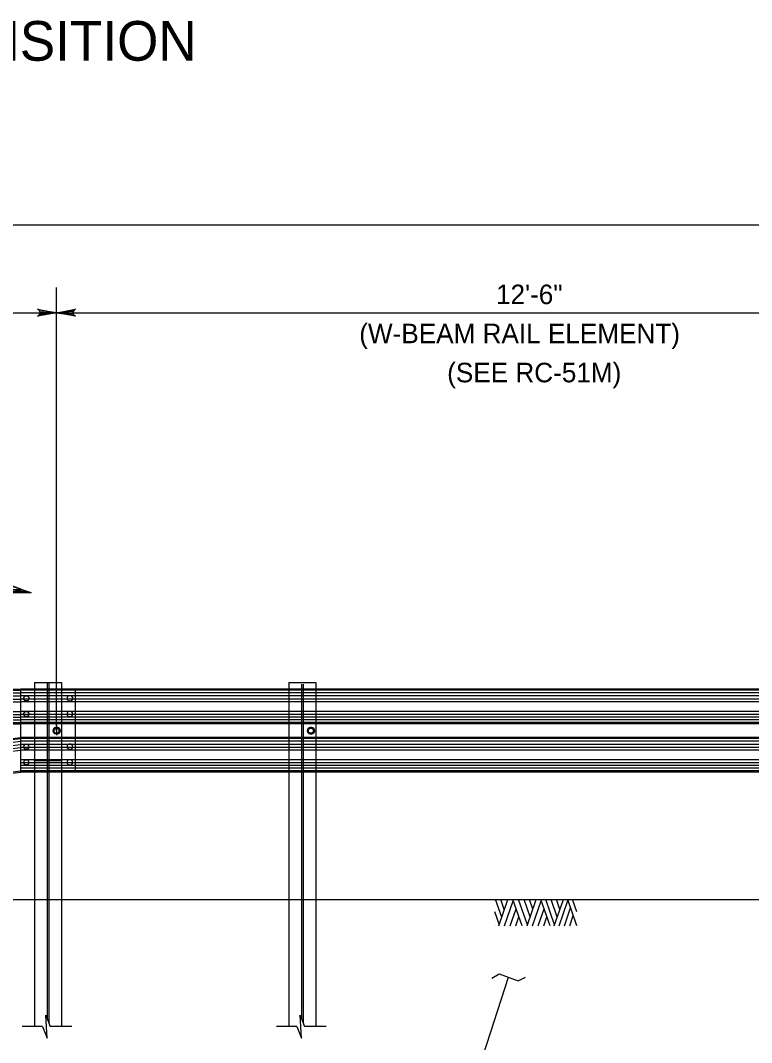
# Model space of a CAD drawing. Extents: x 632007860 to 635435983, y 295418622 to 297794622.
# Drawn here: x 632370402 to 632482682, y 297303010 to 297459928 of the extents above; entities that cross this region are included whole.
import ezdxf

# ---------------------------------------------------------------- set-up
doc = ezdxf.new("R2010")
doc.units = 0
for name, color, linetype in [('2', 7, 'Continuous'), ('S-DETL-DIMS', 7, 'Continuous'), ('S-DETL-T120', 7, 'Continuous'), ('S-DETL-T175', 7, 'Continuous'), ('S-GRND-MAJR', 7, 'Continuous'), ('S-MISC-CNTR-WT01', 7, 'Continuous'), ('S-STEL', 7, 'Continuous')]:
    doc.layers.add(name, color=color, linetype=linetype)

msp = doc.modelspace()

# ---------------------------------------------------------------- linework, layer by layer
at = {"layer": '2'}
for p, q in [((632375953, 297350888), (632375953, 297418941)), ((632413837, 297358026), (632413837, 297306076))]:
    msp.add_line(p, q, dxfattribs=at)
at = {"layer": 'S-DETL-DIMS'}
for p, q in [((632051871, 297428546), (632532195, 297428546)), ((632063630, 297415051), (632529656, 297415051)), ((632442783, 297312872), (632443933, 297313554)), ((632436137, 297284718), (632445379, 297313030)), ((632373809, 297305456), (632370684, 297305456)), ((632378309, 297305456), (632374981, 297305456)), ((632412869, 297305456), (632409744, 297305456)), ((632417370, 297305456), (632414041, 297305456))]:
    msp.add_line(p, q, dxfattribs=at)
for points in [[(632375953, 297415051), (632373040, 297414505), (632373265, 297414660), (632373381, 297414855), (632373414, 297415051), (632373381, 297415246), (632373265, 297415441), (632373040, 297415597), (632375953, 297415051), (632373265, 297415441), (632373381, 297415246), (632375953, 297415051), (632373414, 297415051), (632373381, 297414855), (632375953, 297415051), (632373265, 297414660)], [(632375953, 297415051), (632378866, 297415597), (632378641, 297415441), (632378525, 297415246), (632378492, 297415051), (632378525, 297414855), (632378641, 297414660), (632378866, 297414505), (632375953, 297415051), (632378641, 297414660), (632378525, 297414855), (632375953, 297415051), (632378492, 297415051), (632378525, 297415246), (632375953, 297415051), (632378641, 297415441)], [(632357613, 297372565), (632370633, 297372565), (632361258, 297375977)], [(632361258, 297372565), (632372064, 297372044), (632361594, 297375558)], [(632362734, 297373854), (632372064, 297372044)], [(632357873, 297372305), (632371348, 297372305), (632372064, 297372044), (632358133, 297372044)], [(632443933, 297313554), (632446852, 297312496), (632447979, 297313060)], [(632373809, 297305456), (632374522, 297303698), (632374310, 297307213), (632374981, 297305456)], [(632412869, 297305456), (632413583, 297303698), (632413370, 297307213), (632414041, 297305456)]]:
    msp.add_lwpolyline(points, dxfattribs=at)
msp.add_lwpolyline([(632358133, 297360066), (632357613, 297360066), (632357613, 297372565), (632361258, 297372565), (632361258, 297375977), (632372064, 297372044), (632358133, 297372044)], close=True, dxfattribs=at)
at = {"layer": 'S-GRND-MAJR'}
for p, q in [((632051871, 297324978), (632588398, 297324978)), ((632444307, 297322272), (632443359, 297324960)), ((632443847, 297320953), (632445246, 297324960)), ((632444711, 297323430), (632444185, 297324960)), ((632444749, 297320953), (632446091, 297324774)), ((632447433, 297320953), (632446025, 297324960)), ((632448259, 297321065), (632446898, 297324960)), ((632448691, 297322310), (632447771, 297324960)), ((632448222, 297320953), (632449621, 297324960)), ((632449086, 297323479), (632448579, 297324960)), ((632449057, 297320953), (632450390, 297324761)), ((632451742, 297320953), (632450325, 297324960)), ((632452427, 297321078), (632451066, 297324960)), ((632452831, 297322235), (632451883, 297324960)), ((632452381, 297320953), (632453779, 297324973)), ((632453254, 297323442), (632452728, 297324960)), ((632453132, 297320953), (632454483, 297324836)), ((632455854, 297320953), (632454455, 297324960)), ((632455854, 297323094), (632455206, 297324960)), ((632443932, 297321202), (632443265, 297323094)), ((632445612, 297320953), (632446523, 297323554)), ((632449921, 297320953), (632450822, 297323554)), ((632453958, 297320953), (632454896, 297323679)), ((632446466, 297320953), (632446945, 297322335)), ((632450803, 297320953), (632451263, 297322297)), ((632454756, 297320953), (632455300, 297322534)), ((632443355, 297320953), (632443355, 297320953))]:
    msp.add_line(p, q, dxfattribs=at)
at = {"layer": 'S-MISC-CNTR-WT01'}
for p, q in [((632375953, 297351743), (632375953, 297350177)), ((632372464, 297346307), (632376759, 297346307))]:
    msp.add_line(p, q, dxfattribs=at)
at = {"layer": 'S-STEL'}
for p, q in [((632372563, 297358309), (632376730, 297358309)), ((632372563, 297358309), (632372563, 297357267)), ((632374516, 297358309), (632374516, 297306587)), ((632374776, 297358309), (632374776, 297306076)), ((632376730, 297358309), (632376730, 297357267)), ((632411623, 297358309), (632415791, 297358309)), ((632411623, 297358309), (632411623, 297357267)), ((632411623, 297358309), (632415791, 297358309)), ((632411623, 297358309), (632411623, 297357267)), ((632413577, 297358026), (632413577, 297306587)), ((632415791, 297358309), (632415791, 297357267)), ((632415791, 297358309), (632415791, 297357267)), ((632051871, 297357268), (632370449, 297357268)), ((632051871, 297357099), (632370449, 297357099)), ((632051871, 297356678), (632370449, 297356678)), ((632051871, 297356256), (632370449, 297356256)), ((632580309, 297356678), (632370422, 297356678)), ((632580309, 297357268), (632370449, 297357268)), ((632370449, 297351956), (632370449, 297357268)), ((632580309, 297357099), (632370449, 297357099)), ((632580309, 297356678), (632370449, 297356678)), ((632580309, 297356256), (632370449, 297356256)), ((632371149, 297356256), (632371467, 297356256)), ((632372563, 297357267), (632372563, 297344537)), ((632376730, 297357267), (632376730, 297344537)), ((632378144, 297356256), (632377826, 297356256)), ((632378844, 297344537), (632378844, 297357268)), ((632411623, 297357267), (632411623, 297344537)), ((632415791, 297357267), (632415791, 297344537)), ((632051871, 297355750), (632370449, 297355750)), ((632051871, 297355329), (632370449, 297355329)), ((632580588, 297355750), (632370449, 297355750)), ((632580207, 297355329), (632370449, 297355329)), ((632371484, 297355473), (632371166, 297355473)), ((632377858, 297355473), (632378176, 297355473)), ((632051871, 297353811), (632370449, 297353811)), ((632051871, 297353389), (632370449, 297353389)), ((632051871, 297352968), (632370449, 297352968)), ((632580309, 297353811), (632370449, 297353811)), ((632580309, 297353389), (632370449, 297353389)), ((632580309, 297352968), (632370449, 297352968)), ((632371467, 297353052), (632371149, 297353052)), ((632371166, 297353850), (632371484, 297353850)), ((632378176, 297353850), (632377858, 297353850)), ((632377858, 297353068), (632378176, 297353068)), ((632051871, 297352546), (632370449, 297352546)), ((632051871, 297352125), (632370449, 297352125)), ((632051871, 297351994), (632370449, 297351956)), ((632580309, 297352546), (632370449, 297352546)), ((632580309, 297352125), (632370449, 297352125)), ((632580309, 297351956), (632370449, 297351956)), ((632370449, 297349849), (632370449, 297351956)), ((632376069, 297351357), (632375836, 297351357)), ((632376069, 297351357), (632375836, 297351357)), ((632415130, 297351357), (632414897, 297351357)), ((632415130, 297351357), (632414897, 297351357)), ((632415130, 297351340), (632414897, 297351340)), ((632300133, 297341509), (632370449, 297349680)), ((632300723, 297341707), (632370449, 297349849)), ((632580309, 297349849), (632370449, 297349849)), ((632370449, 297344537), (632370449, 297349849)), ((632580309, 297349680), (632370449, 297349680)), ((632375371, 297350892), (632375371, 297350883)), ((632375371, 297350892), (632375371, 297350883)), ((632375836, 297350418), (632376069, 297350418)), ((632375836, 297350418), (632376069, 297350418)), ((632376535, 297350883), (632376535, 297350892)), ((632376535, 297350883), (632376535, 297350892)), ((632414431, 297350892), (632414431, 297350883)), ((632414431, 297350892), (632414431, 297350883)), ((632414431, 297350874), (632414431, 297350866)), ((632414897, 297350418), (632415130, 297350418)), ((632414897, 297350418), (632415130, 297350418)), ((632414897, 297350400), (632415130, 297350400)), ((632415595, 297350883), (632415595, 297350892)), ((632415595, 297350883), (632415595, 297350892)), ((632415595, 297350866), (632415595, 297350874)), ((632300383, 297341117), (632370449, 297349258)), ((632300383, 297340189), (632370449, 297348331)), ((632301109, 297340695), (632370449, 297348753)), ((632580309, 297349258), (632370449, 297349258)), ((632580309, 297348753), (632370449, 297348753)), ((632580654, 297348331), (632370449, 297348331)), ((632371129, 297348823), (632371447, 297348823)), ((632371487, 297348040), (632371169, 297348040)), ((632378176, 297348823), (632377858, 297348823)), ((632377858, 297348040), (632378176, 297348040)), ((632300383, 297339768), (632370449, 297347909)), ((632580245, 297347909), (632370449, 297347909)), ((632371487, 297346418), (632371169, 297346418)), ((632378176, 297346418), (632377858, 297346418)), ((632580309, 297346392), (632370449, 297346392)), ((632580309, 297345970), (632370449, 297345970)), ((632580309, 297345549), (632370449, 297345549)), ((632580309, 297345127), (632370449, 297345127)), ((632371149, 297346392), (632371467, 297346392)), ((632371467, 297345633), (632371149, 297345633)), ((632377826, 297345633), (632378144, 297345633)), ((632300383, 297336564), (632370430, 297344704)), ((632300723, 297336435), (632370449, 297344537)), ((632580309, 297344706), (632370449, 297344706)), ((632580309, 297344537), (632370449, 297344537)), ((632372563, 297344537), (632372563, 297324977)), ((632376730, 297344537), (632376730, 297324977)), ((632411623, 297344537), (632411623, 297324977)), ((632415791, 297344537), (632415791, 297324977)), ((632372563, 297324977), (632372563, 297305455)), ((632376730, 297324977), (632376730, 297305455)), ((632411623, 297324977), (632411623, 297305455)), ((632415791, 297324977), (632415791, 297305455))]:
    msp.add_line(p, q, dxfattribs=at)
for centre in [(632375953, 297350887), (632415013, 297350887), (632415013, 297350887)]:
    msp.add_circle(centre, 391, dxfattribs=at)
for centre, start, end in [((632375836, 297350892), 90, 180), ((632375836, 297350892), 90, 180), ((632376069, 297350892), 0, 90), ((632376069, 297350892), 0, 90), ((632414897, 297350892), 90, 180), ((632414897, 297350892), 90, 180), ((632414897, 297350874), 90, 180), ((632415130, 297350892), 0, 90), ((632415130, 297350892), 0, 90), ((632415130, 297350874), 0, 90), ((632375836, 297350883), 180, 270), ((632375836, 297350883), 180, 270), ((632376069, 297350883), 270, 360), ((632376069, 297350883), 270, 360), ((632414897, 297350883), 180, 270), ((632414897, 297350883), 180, 270), ((632414897, 297350866), 180, 270), ((632415130, 297350883), 270, 360), ((632415130, 297350883), 270, 360), ((632415130, 297350866), 270, 360)]:
    msp.add_arc(centre, 466, start, end, dxfattribs=at)
for centre, major_axis, start_param, end_param in [((632371165, 297355864), (0, -391), 3.1395093, 6.2852686), ((632371461, 297355864), (0, 391), 3.1395093, 6.2852686), ((632377857, 297355864), (0, 391), 6.281102, 9.4268613), ((632378153, 297355864), (0, -391), 6.281102, 9.4268613), ((632371165, 297353459), (0, -391), 3.1395093, 6.2852686), ((632371461, 297353459), (0, 391), 3.1395093, 6.2852686), ((632377857, 297353459), (0, 391), 6.281102, 9.4268613), ((632378153, 297353459), (0, -391), 6.281102, 9.4268613), ((632371165, 297348432), (0, -391), 3.1395093, 6.2852686), ((632371461, 297348432), (0, 391), 3.1395093, 6.2852686), ((632377857, 297348432), (0, 391), 6.281102, 9.4268613), ((632378153, 297348432), (0, -391), 6.281102, 9.4268613), ((632371165, 297346026), (0, -391), 3.1395093, 6.2852686), ((632371461, 297346026), (0, 391), 3.1395093, 6.2852686), ((632377857, 297346026), (0, 391), 6.281102, 9.4268613), ((632378153, 297346026), (0, -391), 6.281102, 9.4268613)]:
    msp.add_ellipse(centre, major_axis=major_axis, ratio=0.7543445, start_param=start_param, end_param=end_param, dxfattribs=at)

# ---------------------------------------------------------------- texts
at = {"layer": 'S-DETL-T120'}
for s, height, p in [(' 12\'-6"', 2999.8, (632442324, 297416373)), ('(W-BEAM RAIL ELEMENT)', 2999.85, (632422435, 297410373)), ('(SEE RC-51M)', 2999.85, (632435935, 297404373))]:
    msp.add_text(s, height=height, dxfattribs=at).set_placement(p)
at = {"layer": 'S-DETL-T175'}
msp.add_text('ELEVATION VIEW FOR THRIE-BEAM GUIDE RAIL TO BRIDGE BARRIER TRANSITION', height=6096, dxfattribs=at).set_placement((632070911, 297453742))

doc.saveas('drawing.dxf')
